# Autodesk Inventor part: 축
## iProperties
Company: 한국ATC센터
Created: 2015-04
Part Number: 축
Document SubType Name: Modeling
Designer: KYOUNG IL JANG
Density: 1 g/cm^3
Material: 기본값
Mass: 77.3127 g
Surface Area: 163.755 cm^2
Volume: 77.3127 cm^3
Author: KYOUNG IL JANG
